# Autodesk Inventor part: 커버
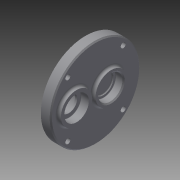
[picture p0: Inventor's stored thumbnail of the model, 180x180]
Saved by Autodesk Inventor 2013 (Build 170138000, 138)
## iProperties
Created: 2015-07
Part Number: 커버
Material: 일반
Document SubType Name: Modeling
Designer: user
Density: 1 g/cm^3
Author: user
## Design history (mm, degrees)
sketch "스케치1"
  geometry: C1 r 40 at (0, 0); 1 further point
  constraints: 1 centre point, 1 coincident
  dimensions: "d0" = 80 diameter of C1
extrude "돌출1" new body sketch "스케치1" distance "d1" = 9; taper "d2" = 0 deg
chamfer "모따기1" distance "d3" = 1; stored, may be unused: second distance "d4" = 2, angle "d5" = 45 deg
sketch "스케치2" dims "d7" = 70
  geometry: L1 (0, 0)-(-37.073, 37.073); L2 (0, 0)-(-47.926, 0); C1 r 40 at (0, 0) reference; 5 further points
  constraints: 4 end point, 1 coincident, 1 horizontal, 1 point on line, 8 other
  dimensions: "d6" = 45 deg angle of L2 L1; "d10" = 360 deg dimension on point (0, 0) point (-24.749, 24.749) (derived)
hole "구멍1" sketch "스케치2" at (-24.749, 24.749), (-24.749, -24.749), (24.749, -24.749), (24.749, 24.749) diameter "d12" = 4.5; stored, may be unused: countersink angle "d16" = 90 deg, drill point angle "d18" = 118 deg; dims "d13" = 6, "d14" = 8, "d15" = 4.4, "d17" = 8
sketch "스케치3"
  geometry: L1 (0, 0)-(0, -20); C1 r 40 at (0, 0) reference; C2 r 15 at (0, -20)
  constraints: 2 end point, 1 centre point, 1 coincident, 1 vertical
  dimensions: "d19" = 20 distance of L1.start L1.end; "d20" = 30 diameter of C2
extrude "돌출2" join sketch "스케치3" distance "d21" = 4; taper "d22" = 0 deg
sketch "스케치4"
  geometry: L1 (0, 0)-(0, -20); L2 (0, 0)-(0, 11); C1 r 39 at (0, 0) reference; C2 r 14 at (0, -20); C3 r 14 at (0, 11)
  constraints: 4 end point, 2 centre point, 2 coincident, 1 collinear, 1 vertical
  dimensions: "d23" = 20 distance of L1.start L1.end; "d24" = 28 diameter of C2; "d25" = 11 distance of L1.start L2.end; "d26" = 28 diameter of C3
extrude "돌출3" join sketch "스케치4" distance "d27" = 3; taper "d28" = 0 deg
fillet "모깎기1" dims "d29" = 2
sketch "스케치5"
  geometry: C1 r 14 at (0, 0) reference; 1 further point
hole "구멍2" sketch "스케치5" at (0, 0) diameter "d30" = 22; stored, may be unused: countersink angle "d34" = 90 deg, drill point angle "d36" = 0 deg; dims "d31" = 6, "d32" = 8, "d33" = 4.4, "d35" = 7
sketch "스케치6"
  geometry: 2 further points
  constraints: 1 vertical alignment
hole "구멍3" sketch "스케치6" at (0, 0) diameter "d37" = 18; stored, may be unused: countersink angle "d41" = 90 deg, drill point angle "d43" = 0 deg; dims "d38" = 6, "d39" = 8, "d40" = 4.4, "d42" = 1
fillet "모깎기2" dims "d44" = 1
chamfer "모따기2" distance "d45" = 1; stored, may be unused: second distance "d46" = 2, angle "d47" = 45 deg
fillet "모깎기3" dims "d48" = 0.3
sketch "스케치7"
  geometry: C1 r 14 at (0, 0) reference; 1 further point
hole "구멍4" sketch "스케치7" at (0, 0) diameter "d49" = 15; stored, may be unused: countersink angle "d53" = 90 deg, drill point angle "d55" = 0 deg; dims "d50" = 6, "d51" = 22, "d52" = 7, "d54" = 1
sketch "스케치8"
  geometry: C1 r 7.5 at (0, 0) reference; 1 further point
hole "구멍5" sketch "스케치8" at (0, 0) diameter "d56" = 15; stored, may be unused: countersink angle "d60" = 90 deg, drill point angle "d62" = 0 deg; dims "d57" = 6, "d58" = 22, "d59" = 7, "d61" = 1
fillet "모깎기4" dims "d63" = 0.3
node "솔리드1"
